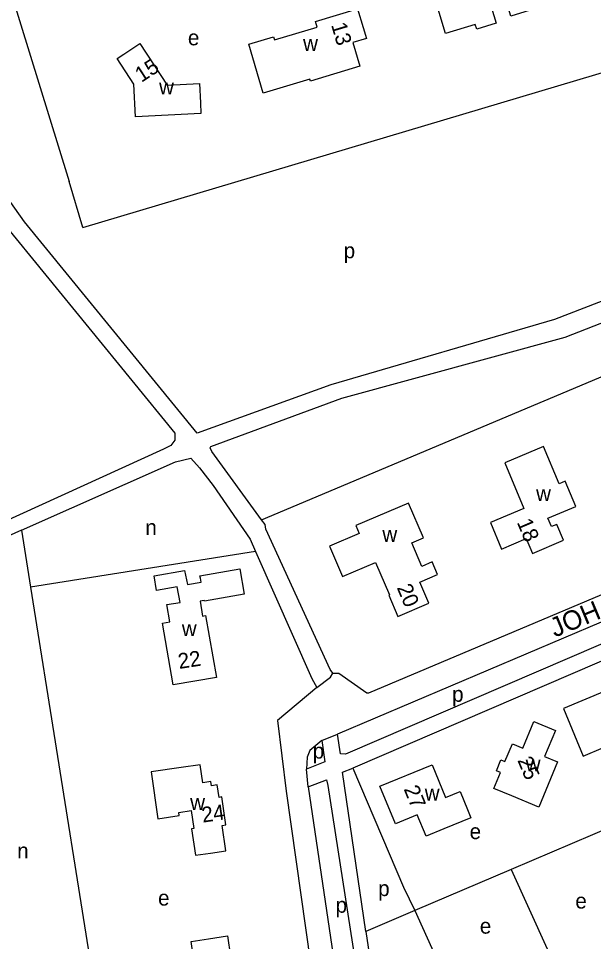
# Model space of a CAD drawing. Extents: x 162427 to 165104, y 384242 to 386287.
# Drawn here: x 163093 to 163242.2, y 384850.5 to 385090 of the extents above; entities that cross this region are included whole.
import ezdxf

# ---------------------------------------------------------------- set-up
doc = ezdxf.new("R2010")
doc.units = 0
for name, color, linetype in [('BLT_Basislijn', 7, 'Continuous'), ('BLT_Bebouwing', 7, 'Continuous'), ('BLT_Centroide', 7, 'Continuous'), ('BLT_Huisnummer', 7, 'Continuous'), ('BLT_Straatnaam', 7, 'Continuous')]:
    doc.layers.add(name, color=color, linetype=linetype)

msp = doc.modelspace()

# ---------------------------------------------------------------- linework, layer by layer
at = {"layer": 'BLT_Basislijn'}
for p, q in [((163109.64, 385035.76), (163280.79, 385086.83)), ((163109.64, 385035.76), (163106.15, 385047.69)), ((163093.78, 384957.23), (163096.13, 384942.44)), ((163154.51, 384951.76), (163096.13, 384942.44)), ((163171.73, 384902.72), (163175.78, 384904.36)), ((163168.17, 384890.67), (163167.69, 384895.23)), ((163220.86, 384869.18), (163195.79, 384858.55)), ((163195.79, 384858.55), (163183.14, 384853.15)), ((163183.14, 384853.15), (163190.13, 384805.87))]:
    msp.add_line(p, q, dxfattribs=at)
for points in [[(163025.44, 384989.04), (163024.5, 385030.84), (163018.89, 385076.44), (163017.02, 385103.67), (163017.23, 385122.42), (163017.79, 385132.63), (163019.43, 385149.85), (163022.64, 385150.23), (163027.16, 385135.24), (163031.42, 385124.02), (163037.11, 385112.38), (163045.09, 385098.64), (163088.89, 385037.1), (163133.57, 384982.4), (163133.57, 384980.59), (163132.55, 384979.22), (163130.59, 384978.25), (163055.8, 384944.22)], [(163080.24, 385131.33), (163106.15, 385047.69)], [(163280.79, 385086.83), (163287.27, 385068.91), (163302.81, 385042.19), (163304.2, 385039.78), (163302.8, 385039.26), (163232.03, 385011.91), (163174.05, 384994.99), (163139.33, 384982.45), (163094.55, 385037.28), (163050.17, 385099.92)], [(163156.05, 384959.92), (163143.17, 384977.66), (163142.73, 384978.59), (163142.89, 384979), (163176.85, 384991.5), (163234.86, 385007.37), (163302.78, 385033.87), (163306.17, 385035.19), (163306.77, 385035.11), (163319.47, 385014.55), (163323.92, 385005.33), (163328.98, 384992.2), (163330.16, 384988.47), (163332.76, 384977.48)], [(163156.05, 384959.92), (163302.74, 385021.67), (163308.88, 385023.89), (163329.05, 384975.86)], [(163093.78, 384957.23), (163133.76, 384974.97), (163137.7, 384975.98), (163139.96, 384973.46), (163143.45, 384968.82), (163153.12, 384954.9), (163154.51, 384951.76)], [(163174.52, 384920.17), (163176.12, 384920.16), (163183.37, 384915.07), (163183.91, 384915.07), (163302.53, 384965.17), (163329.05, 384975.86)], [(163335.15, 384971.31), (163336.81, 384966.89), (163336.59, 384966.26), (163302.48, 384952.34), (163243.99, 384927.63), (163177.81, 384899.17), (163176.54, 384899.27), (163175.78, 384904.36)], [(163335.15, 384971.31), (163302.5, 384957.77), (163244.16, 384933.41), (163175.78, 384904.36)], [(163350, 384938.77), (163337.83, 384961.72), (163337.03, 384962.14), (163336.25, 384962.03), (163302.47, 384948.03), (163279.02, 384938.27), (163179.71, 384895.48)], [(163174.52, 384920.17), (163173.84, 384921.07), (163157.2, 384957.53), (163156.96, 384958.77), (163156.05, 384959.92)], [(163093.78, 384957.23), (163068.12, 384945.78), (163050.93, 384936.2)], [(163154.51, 384951.76), (163169.09, 384918.8), (163170.37, 384916.41)], [(163096.13, 384942.44), (163117.13, 384810.65), (163117.49, 384810.25), (163172.53, 384818.04)], [(163170.37, 384916.41), (163173.96, 384919.16), (163174.52, 384920.17)], [(163170.37, 384916.41), (163160.16, 384907.85), (163162.45, 384889.54), (163172.53, 384818.04)], [(163171.73, 384902.72), (163172.46, 384897.17), (163167.69, 384895.23)], [(163171.73, 384902.72), (163168.55, 384900.06), (163167.89, 384898.36), (163167.69, 384895.23)], [(163183.14, 384853.15), (163177.09, 384894.43), (163179.71, 384895.48)], [(163179.71, 384895.48), (163192.86, 384864.6), (163195.79, 384858.55)], [(163168.17, 384890.67), (163172.94, 384892.49), (163173.27, 384891.04), (163186.69, 384804.78)], [(163168.17, 384890.67), (163180.11, 384810.14), (163180.73, 384807.82), (163182.83, 384805.47), (163184.52, 384804.9), (163186.69, 384804.78)], [(163247.18, 384880.45), (163220.86, 384869.18)], [(163220.86, 384869.18), (163239.54, 384828.04), (163239.73, 384827.14), (163238.88, 384826.47), (163226.25, 384820.99)], [(163195.79, 384858.55), (163214.6, 384817.02), (163214.41, 384816.06)]]:
    msp.add_lwpolyline(points, dxfattribs=at)
at = {"layer": 'BLT_Bebouwing'}
for points in [[(163226.59, 385097.34), (163227.96, 385092.87), (163220.69, 385090.65), (163219.67, 385094.01), (163215.68, 385092.79), (163216.91, 385088.76), (163211.88, 385087.23), (163211.5, 385088.47), (163203.78, 385086.11), (163201.58, 385093.33), (163200.12, 385098.11), (163212.28, 385101.83), (163213.72, 385097.11), (163219.06, 385098.74), (163218.63, 385100.14), (163225.13, 385102.12), (163226.59, 385097.34)], [(163170.47, 385087.74), (163170.03, 385089.24), (163180.98, 385092.5), (163182.4, 385087.71)], [(163168.56, 385074.28), (163156.5, 385070.68), (163152.72, 385083.36), (163159.19, 385085.29), (163159.44, 385084.45), (163170.47, 385087.74)], [(163182.4, 385087.71), (163183.27, 385084.81), (163179.74, 385083.76), (163181.57, 385077.61), (163168.71, 385073.77), (163168.56, 385074.28)], [(163140.17, 385068.13), (163140.32, 385065.36), (163123.38, 385064.46), (163122.93, 385072.99), (163118.58, 385079.67), (163120.29, 385080.78), (163124.48, 385083.5), (163131.52, 385072.68), (163139.91, 385073.12), (163140.17, 385068.13)], [(163234.4, 384954.63), (163232.66, 384958.75), (163231.3, 384958.18), (163230.37, 384960.38), (163237.59, 384963.43), (163234.83, 384969.94), (163233.27, 384969.28), (163229.17, 384978.98), (163219.21, 384974.77), (163224.07, 384962.87), (163215.42, 384959.24), (163218.33, 384952.35), (163224.75, 384955.07), (163226.37, 384951.24), (163234.4, 384954.63)], [(163197.62, 384947.87), (163195.02, 384953.98), (163198.05, 384955.27), (163194.21, 384964.28), (163180.51, 384958.45)], [(163180.51, 384958.45), (163181.4, 384956.36), (163173.69, 384953.08), (163177.03, 384945.23)], [(163177.03, 384945.23), (163185.63, 384948.9), (163189.22, 384940.47), (163189.04, 384940.39), (163191.39, 384934.87), (163199.42, 384938.29), (163197.08, 384943.78), (163201.74, 384945.76), (163200.35, 384949.03), (163197.62, 384947.87)], [(163232.28, 384905.31), (163229.49, 384898.52), (163232.86, 384897.13), (163228.02, 384885.38), (163220.95, 384888.29), (163216.33, 384890.2), (163218.06, 384894.4), (163216.97, 384894.85), (163218.13, 384897.66), (163219.21, 384897.22), (163221.12, 384901.84), (163223.85, 384900.72), (163226.69, 384907.62), (163232.28, 384905.31)], [(163142.77, 384873.48), (163146.8, 384874.07), (163145.84, 384880.64), (163146.77, 384880.78), (163145.71, 384888.03), (163145.02, 384887.93), (163144.55, 384891.15), (163143.04, 384890.93), (163142.88, 384892.01), (163140.83, 384891.71), (163140.14, 384896.41), (163135.19, 384895.69), (163127.39, 384894.55), (163129.17, 384882.4), (163134.66, 384883.2), (163134.54, 384884.02), (163137.82, 384884.49), (163138.5, 384879.84), (163137.87, 384879.75), (163138.87, 384872.91), (163142.77, 384873.48)], [(163209.46, 384884.82), (163210.36, 384882.63), (163203.35, 384879.74), (163198.72, 384877.84), (163196.44, 384883.38), (163190.77, 384881.05), (163186.75, 384890.81), (163200.31, 384896.39), (163203.81, 384887.9), (163207.55, 384889.45), (163209.46, 384884.82)], [(163151.85, 384847.18), (163154, 384832.87), (163152.72, 384832.68), (163153.31, 384828.76), (163146.47, 384827.74), (163145.89, 384831.65), (163144.51, 384831.45), (163144.29, 384832.96), (163145.35, 384833.12), (163144.82, 384836.66), (163143.8, 384836.51), (163142.7, 384843.85), (163138.84, 384843.27), (163137.74, 384850.57), (163142.26, 384851.25), (163147.21, 384851.99), (163148.01, 384846.61), (163151.85, 384847.18)]]:
    msp.add_lwpolyline(points, dxfattribs=at)
for points in [[(163133.14, 384917.12), (163130.32, 384933.15), (163132.29, 384933.5), (163131.51, 384937.93), (163134.89, 384938.53), (163134.18, 384942.53), (163128.8, 384941.61), (163128.15, 384945.42), (163136.08, 384946.78), (163136.8, 384943.19), (163140.34, 384943.79), (163140.17, 384944.79), (163140.07, 384945.37), (163150.39, 384947.19), (163151.53, 384940.69), (163141.21, 384938.87), (163141.17, 384939.03), (163140.11, 384938.85), (163140.76, 384934.95), (163141.54, 384935.14), (163144.37, 384919.07)], [(163256.55, 384920.28), (163234.4, 384911.01), (163239.51, 384898.65), (163250.09, 384903.08), (163248.72, 384906.35), (163254.47, 384908.75), (163254.65, 384908.33), (163254.93, 384908.45), (163255.31, 384907.55), (163254.79, 384907.33), (163255.8, 384904.92), (163260.17, 384906.74), (163259.95, 384907.25), (163261.71, 384907.98), (163259.2, 384913.97), (163259.73, 384914.2), (163258.6, 384916.85), (163258.08, 384916.62)]]:
    msp.add_lwpolyline(points, close=True, dxfattribs=at)

# ---------------------------------------------------------------- texts
at = {"layer": 'BLT_Centroide'}
for s, p in [('e', (163136.94, 385083.05)), ('w', (163166.82, 385081.59)), ('w', (163129.45, 385070.33)), ('p', (163177.36, 385027.81)), ('w', (163227.28, 384964.82)), ('n', (163125.89, 384956)), ('w', (163187.39, 384954.22)), ('w', (163135.36, 384929.79)), ('p', (163205.49, 384912.73)), ('p', (163169.33, 384898)), ('w', (163224.59, 384894.66)), ('w', (163198.39, 384887.12)), ('w', (163137.52, 384884.66)), ('e', (163210.04, 384877.1)), ('n', (163092.64, 384872.09)), ('p', (163186.3, 384862.32)), ('e', (163129.2, 384859.86)), ('p', (163175.26, 384858)), ('e', (163237.47, 384859.09)), ('e', (163212.69, 384852.57))]:
    msp.add_text(s, height=4, dxfattribs=at).set_placement(p)
at = {"layer": 'BLT_Huisnummer'}
for s, rotation, p in [('13', 286.6081, (163174.06, 385088.37)), ('15', 33.0416, (163124.86, 385073.3)), ('18', 292.9063, (163222.24, 384959.31)), ('20', 293.0636, (163191.08, 384942.35)), ('22', 8.686, (163134.68, 384921.24)), ('25', 292.7847, (163222.38, 384897.57)), ('27', 292.3577, (163192.87, 384890.11)), ('24', 8.3151, (163140.8, 384881.37))]:
    msp.add_text(s, height=4, rotation=rotation, dxfattribs=at).set_placement(p)
at = {"layer": 'BLT_Straatnaam'}
msp.add_text('JOHAN DE WITTLAAN', height=5, rotation=22.6558, dxfattribs=at).set_placement((163232.15, 384929.36))

doc.saveas('drawing.dxf')
